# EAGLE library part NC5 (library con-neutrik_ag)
Neutrik Audio Connector XLR SERIES Stereo 1/4" jack Source: www.neutrik.com/
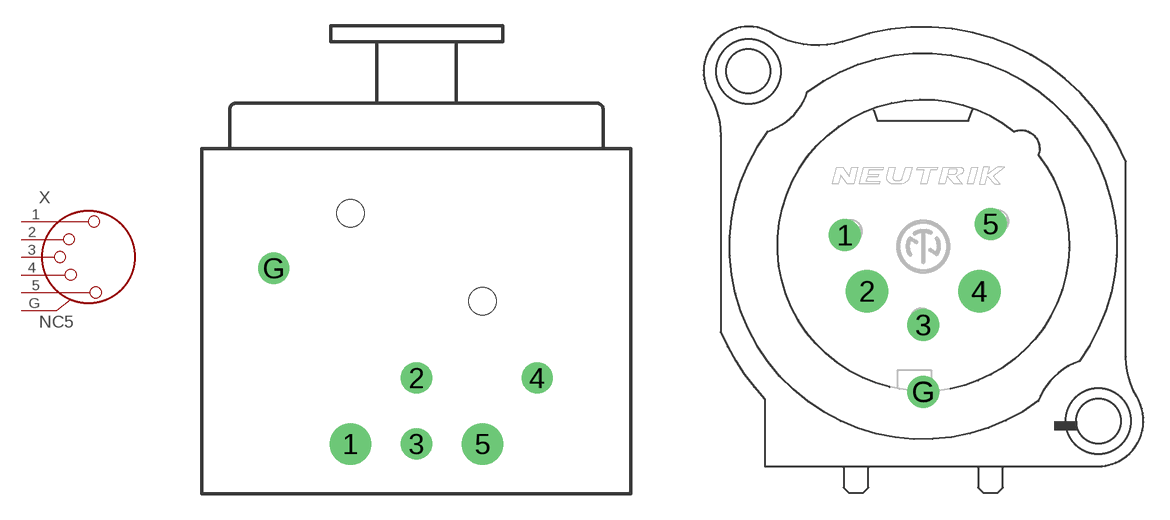
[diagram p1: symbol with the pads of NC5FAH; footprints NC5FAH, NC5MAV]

Designator prefix X

## NC5FAH (MF: FARNELL; MPN: NC5FAH; OC_FARNELL: 8020418; OC_NEWARK: 38K6010)  [NC5FAH]
1  1  pas
2  2  pas
3  3  pas
4  4  pas
5  5  pas
G  G  pas

## NC5MAV (MPN: NC5MAV; OC_FARNELL: unknown; OC_NEWARK: 86C7397)  [NC5MAV]
Pads as for NC5FAH

## NC5FBH (MPN: NC5FBH; OC_FARNELL: 8314616; OC_NEWARK: 73C3494)  [NC5FBH]
Pads as for NC5FAH

## NC5FBH-B (OC_FARNELL: unknown; OC_NEWARK: unknown)  [NC5FBH-B]
Pads as for NC5FAH

## NC5FBV (MPN: NC5FBV; OC_FARNELL: 8314632; OC_NEWARK: 87K0089)  [NC5FBV]
Pads as for NC5FAH

## NC5FGV-B (OC_FARNELL: unknown; OC_NEWARK: unknown)  [NC5FBV-B]
Pads as for NC5FAH

## NC5MAH (MF: FARNELL; MPN: NC5MAH; OC_FARNELL: 8020396; OC_NEWARK: 38K6012)  [NC5MAH]
Pads as for NC5FAH

## NC5MBH (MPN: NC5MBH; OC_FARNELL: 8314624; OC_NEWARK: 92K7339)  [NC5MBH]
Pads as for NC5FAH

## NC5MBN-B (OC_FARNELL: unknown; OC_NEWARK: unknown)  [NC5MBH-B]
Pads as for NC5FAH

## NC5MBV (MPN: NC5MBV; OC_FARNELL: 8314640; OC_NEWARK: 92K7340)  [NC5MBV]
Pads as for NC5FAH

## NC5FAV (MPN: NC5FAV; OC_FARNELL: unknown; OC_NEWARK: 94C1526)  [NC5FAV]
Pads as for NC5FAH

## Footprint NC5FAH (pad centres in mm)
Neutrik Audio Connector Source: www.neutrik.com/... 210_142701.pdf
drill 1.6 round: 1 -3.81,-3.815; 5 3.81,-3.815
drill 1.2 round: 2 0,0; 3 0,-3.815; 4 6.98,0; G -8.25,6.355
hole 1.6 at 3.81,4.445
hole 1.6 at -3.81,9.525

## Footprint NC5MAV (pad centres in mm)
Neutrik Audio Connector Source: www.neutrik.com/... 210_257601.pdf
drill 1.2 round: 1 -4.445,0.635; 3 0,-4.445; 5 3.81,1.27; G 0,-8.225
drill 1.6 round: 2 -3.175,-2.54; 4 3.175,-2.54

## Footprint NC5FBH (pad centres in mm)
Neutrik Audio Connector Source: www.neutrik.com/... 210_2351.pdf
drill 1.6 round: 1 -3.81,-3.815; 5 3.81,-3.815
drill 1.2 round: 2 0,0; 3 0,-3.815; 4 6.98,0; G -8.25,6.355
hole 1.6 at 3.81,4.445
hole 1.6 at -3.81,11.43

## Footprint NC5FBH-B (pad centres in mm)
Neutrik Audio Connector Source: www.neutrik.com/... 210_1401.pdf
drill 1.6 round: 1 -3.81,-3.815; 5 3.81,-3.815
drill 1.2 round: 2 0,0; 3 0,-3.815; 4 6.98,0; G -8.25,6.355
hole 1.6 at 3.81,4.445
hole 1.6 at -3.81,11.43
